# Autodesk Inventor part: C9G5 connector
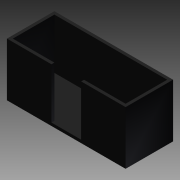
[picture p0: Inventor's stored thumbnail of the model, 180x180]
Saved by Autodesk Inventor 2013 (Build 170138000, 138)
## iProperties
Company: Autodesk Inc.
Created: 2005-12
Part Number: C9G5 connector
Document SubType Name: Modeling
Designer: Autodesk Inc.
Density: 1 g/cm^3
Mass: 0.28825 g
Surface Area: 11.895 cm^2
Volume: 0.28825 cm^3
Material: Allgemein
Title: Personal Computer
Author: Autodesk Inc.
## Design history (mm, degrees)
sketch "Sketch1"
  geometry: L1 (0, 5.6)-(0, -5.6) reference; L2 (-14, 0)-(14, 0) reference; L3 (-10, 4)-(10, 4); L4 (10, 4)-(10, -4); L5 (10, -4)-(-10, -4); L6 (-10, -4)-(-10, 4)
  constraints: 8 end point, 2 parallel, 1 horizontal, 1 perpendicular, 2 other
  dimensions: "d0" = 20 distance of L4.end L5.end; "d1" = 8 distance of L5.end L3.start
extrude "Extrusion1" new body sketch "Sketch1" distance "d2" = 9; taper "d3" = 0 deg
shell "Shell1" dims "d4" = 0.5
sketch "Sketch2"
  geometry: L1 (20, 9)-(0, 9) reference; L2 (19.5, 0.5)-(0.5, 0.5) reference; L3 (10, 10.8)-(10, -1.8) reference; L4 (7.5, 9)-(12.5, 9); L5 (12.5, 9)-(12.5, 0.5); L6 (12.5, 0.5)-(7.5, 0.5); L7 (7.5, 0.5)-(7.5, 9)
  constraints: 8 end point, 2 parallel, 2 point on line, 1 horizontal, 1 perpendicular, 1 other
  dimensions: "d5" = 5 distance between parallel lines of L5 L7
extrude "Extrusion2" cut sketch "Sketch2" stored distance "d6" = 9; taper "d7" = 0 deg
body "Solid1"
